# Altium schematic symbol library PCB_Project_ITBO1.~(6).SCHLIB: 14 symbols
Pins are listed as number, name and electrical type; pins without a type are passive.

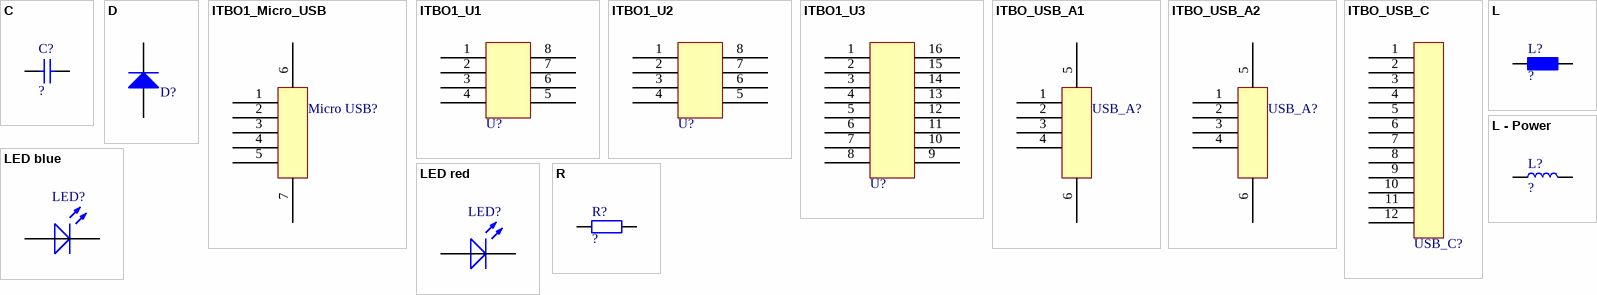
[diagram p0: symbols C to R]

## C
designator C?, comment ?
Capacitor; #Manufacturer: Generic Components; #Publisher: Dr. A. Heinzelmann; #Class: Passive; Initial Voltage: 0V
simulation model CAP (Capacitor)
pins: 1, 2

## D
designator D?
Switching Diode; Manufacturer: Diodes Incorporated; Manufacturer PartNr: 1N4148W-7-F
footprint DIODES_SOD123_2_H
pins: 1 K, 2 A

## ITBO1_Micro_USB
designator Micro USB?  (value not drawn)
pins: 1, 2, 3, 4, 5, 6, 7

## ITBO1_U1
designator U?  (value not drawn)
footprint ITBO1_U1 (TSOP, 8-Leads, Body 4.85x3.85mm, Pitch 1.27mm, IPC Medium Density)
pins: 1, 2, 3, 4, 5, 6, 7, 8

## ITBO1_U2
designator U?  (value not drawn)
footprint ITBO1_U2 (TSOP, 8-Leads, Body 4.85x3.85mm, Pitch 1.27mm, IPC Medium Density)
pins: 1, 2, 3, 4, 5, 6, 7, 8

## ITBO1_U3
designator U?  (value not drawn)
footprint ITBO1_U3
pins: 1, 2, 3, 4, 5, 6, 7, 8, 9, 10, 11, 12, 13, 14, 15, 16

## ITBO_USB_A1
designator USB_A?  (value not drawn)
pins: 1, 2, 3, 4, 5, 6

## ITBO_USB_A2
designator USB_A?  (value not drawn)
pins: 1, 2, 3, 4, 5, 6

## ITBO_USB_C
designator USB_C?  (value not drawn)
pins: 1, 2, 3, 4, 5, 6, 7, 8, 9, 10, 11, 12

## L
designator L?  (value not drawn)
Inductor; #Manufacturer: Generic Components; #Publisher: Dr. A. Heinzelmann; #Class: Passive; #ClassSub: Resistor
pins: 1, 2

## L - Power
designator L?, comment ?
Inductor - Power; #Manufacturer: Generic Components; #Publisher: Dr. A. Heinzelmann; #Class: Passive; #ClassSub: Resistor
simulation model Inductor (ideal Inductor)
footprint WE-TPC (Power-Choke WE-TPC 2.8 x 2.8)
pins: 1, 2

## LED blue
designator LED?, comment tbd  (value not drawn)
LED blue; Manufacturer: generic; #ClassSub: LEDs; #Class: Generic-Components
pins: 1 K, 2 A

## LED red
designator LED?, comment tbd  (value not drawn)
LED red; Manufacturer: generic; #ClassSub: LEDs; #Class: Generic-Components
pins: 1 K, 2 A

## R
designator R?, comment ?
Resistor; #Manufacturer: Generic Components; #Publisher: Dr. A. Heinzelmann; #Class: Passive
pins: 1, 2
